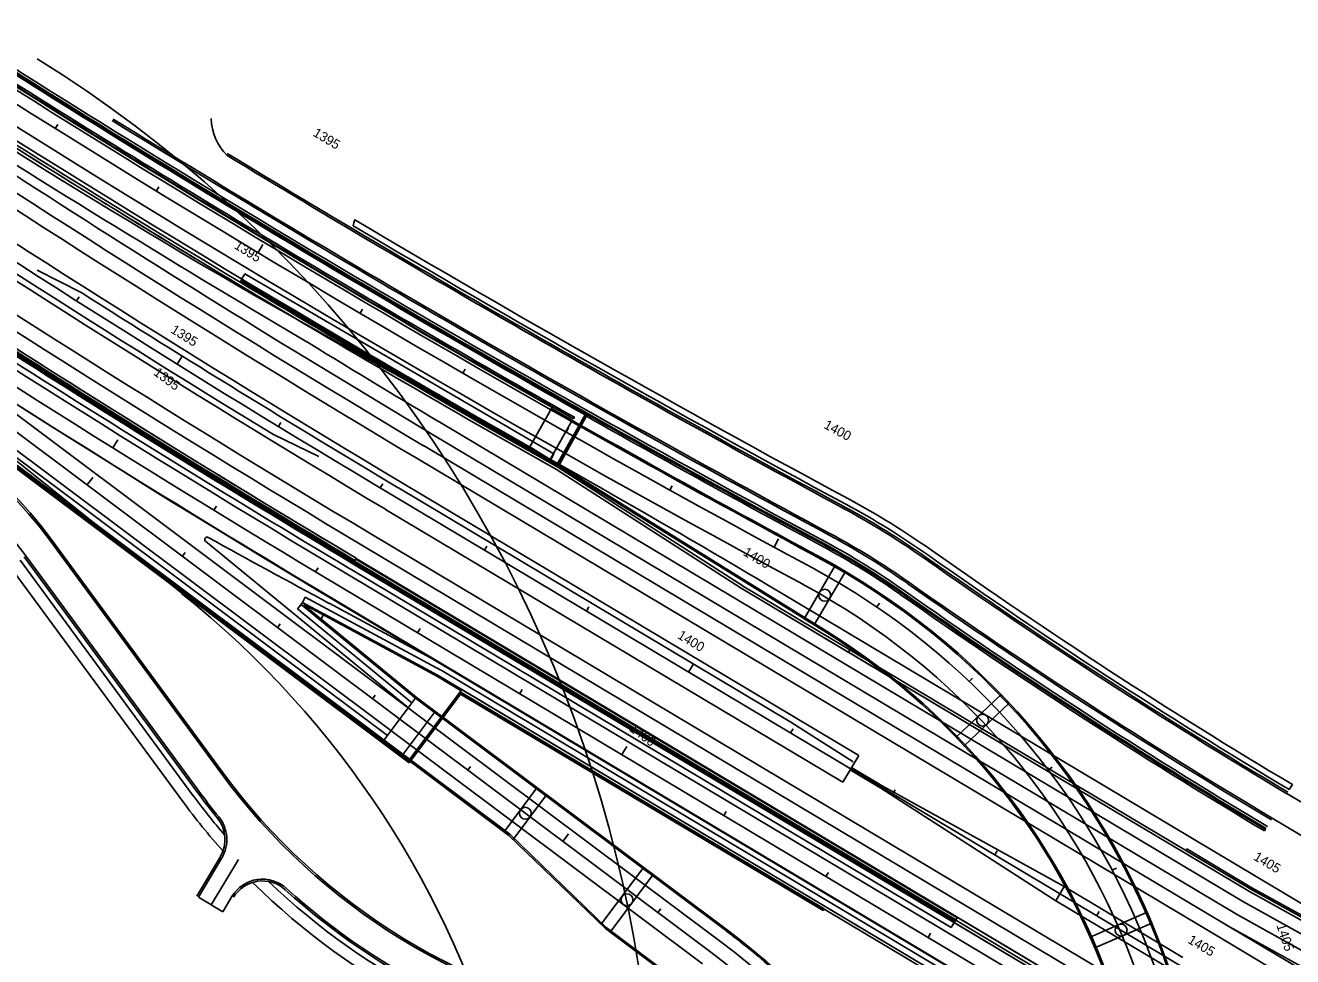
# Model space of a CAD drawing. Extents: x 2339272 to 2351734, y 366540 to 375057.
# Drawn here: x 2345972 to 2347038, y 369498 to 370281 of the extents above; entities that cross this region are included whole.
import ezdxf

# ---------------------------------------------------------------- set-up
doc = ezdxf.new("R2010")
doc.units = 0
for name, color, linetype in [('RD_HC_Cl', 7, 'Continuous'), ('RD_HC_CL_Rel', 7, 'Continuous'), ('RD_HC_Data_Tic', 7, 'Continuous'), ('RD_HC_Data_Tic_Rel', 7, 'Continuous'), ('RD_HC_TX_Rel_Sta50', 7, 'Continuous'), ('RD_HC_TX_Sta50', 7, 'Continuous'), ('RD_PD_Bridge', 7, 'Continuous'), ('RD_PD_Final_LnLine', 7, 'Continuous'), ('RD_PD_Final_TrvlWay', 7, 'Continuous'), ('RD_PD_FOC', 7, 'Continuous'), ('RD_PD_MedBWall', 7, 'Continuous'), ('RD_PD_MedGR', 7, 'Continuous'), ('RD_PD_NOISE-WALL-GM', 7, 'Continuous'), ('RD_PD_PaveShd', 7, 'Continuous'), ('RD_PD_SW', 7, 'Continuous'), ('RD_PD_WallFill', 7, 'Continuous')]:
    doc.layers.add(name, color=color, linetype=linetype)

msp = doc.modelspace()

# ---------------------------------------------------------------- linework, layer by layer
at = {"layer": 'RD_HC_Cl'}
for p, q in [((2345614.6, 370194.7), (2346103.4, 369803.5)), ((2345614.6, 370194.7), (2346103.4, 369803.5)), ((2345614.6, 370194.7), (2346103.4, 369803.5)), ((2345614.6, 370194.7), (2346103.4, 369803.5)), ((2345717.1, 370123.9), (2346548.7, 369501.6)), ((2346281.6, 369885.4), (2351112.4, 367003.2)), ((2346606.5, 369804.5), (2348463.1, 368696.8)), ((2346606.5, 369804.5), (2348463.1, 368696.8)), ((2346606.5, 369804.5), (2348463.1, 368696.8)), ((2346606.5, 369804.5), (2348463.1, 368696.8))]:
    msp.add_line(p, q, dxfattribs=at)
for centre, radius, start, end in [((2352034, 379865.6), 11400.7, 232.99132, 241.72492), ((2352152.8, 379726.2), 11459.2, 233.26372, 239.17851), ((2349158.4, 375253.9), 6000, 236.19528, 241.60251), ((2349158.4, 375253.9), 6000, 236.19528, 241.60251), ((2349158.4, 375253.9), 6000, 236.19528, 241.60251), ((2349158.4, 375253.9), 6000, 236.19528, 241.60251), ((2345401.1, 369318.9), 1100, 337.175, 58.1352), ((2345401.1, 369318.9), 1100, 337.175, 58.1352), ((2345401.1, 369318.9), 1100, 337.175, 58.1352), ((2345401.1, 369318.9), 1100, 337.175, 58.1352), ((2342405.1, 362762.6), 8200, 59.17851, 61.60251), ((2342405.1, 362762.6), 8200, 59.17851, 61.60251), ((2342405.1, 362762.6), 8200, 59.17851, 61.60251), ((2342405.1, 362762.6), 8200, 59.17851, 61.60251), ((2346341.6, 369282.7), 616, 339.5935, 61.7249), ((2345603.4, 369178.9), 800, 339.7746, 51.3248), ((2345603.4, 369178.9), 800, 339.7746, 51.3248), ((2345603.4, 369178.9), 800, 339.7746, 51.3248), ((2345603.4, 369178.9), 800, 339.7746, 51.3248), ((2346182, 369011.6), 612, 321.0938, 53.1918)]:
    msp.add_arc(centre, radius, start, end, dxfattribs=at)
at = {"layer": 'RD_HC_CL_Rel'}
for p, q in [((2346236.3, 369809.5), (2347935.6, 368795.6)), ((2346990.8, 369533.5), (2347672.4, 369155.9))]:
    msp.add_line(p, q, dxfattribs=at)
msp.add_arc((2352152.8, 379726.2), 11547.6, 233.26372, 239.17851, dxfattribs=at)
at = {"layer": 'RD_HC_Data_Tic'}
for p, q in [((2345997, 370194.5), (2345999.1, 370197.9)), ((2346082.1, 370141.9), (2346084.2, 370145.3)), ((2346167.6, 370090.1), (2346171.7, 370096.9)), ((2346015, 370049.4), (2346017.2, 370052.8)), ((2346253.6, 370039), (2346255.6, 370042.4)), ((2346099.7, 369996.2), (2346103.9, 370003)), ((2346340, 369988.7), (2346342, 369992.1)), ((2346184.8, 369943.8), (2346186.9, 369947.2)), ((2346426.8, 369939.1), (2346428.8, 369942.6)), ((2346023.7, 369894.4), (2346028.5, 369900.8)), ((2346270.4, 369892.1), (2346272.5, 369895.5)), ((2346514.1, 369890.3), (2346516.1, 369893.8)), ((2346601.8, 369842.3), (2346605.6, 369849.3)), ((2346103.8, 369834.5), (2346106.2, 369837.7)), ((2346358.1, 369839.8), (2346360.1, 369843.2)), ((2346688.2, 369792), (2346690.4, 369795.3)), ((2346443.9, 369788.6), (2346446, 369792)), ((2346183.9, 369774.5), (2346186.3, 369777.7)), ((2346529.8, 369737.3), (2346533.9, 369744.2)), ((2346765.9, 369729.3), (2346768.7, 369732.2)), ((2346263.9, 369714.6), (2346266.3, 369717.8)), ((2346615.7, 369686.1), (2346617.7, 369689.5)), ((2346344, 369654.7), (2346346.4, 369657.9)), ((2346832.5, 369654.8), (2346835.7, 369657.2)), ((2346701.6, 369634.8), (2346703.6, 369638.3)), ((2346424.1, 369594.8), (2346428.9, 369601.2)), ((2346787.5, 369583.6), (2346789.5, 369587)), ((2346886.2, 369570.6), (2346889.8, 369572.4)), ((2346504.1, 369534.9), (2346506.5, 369538.1)), ((2346873.3, 369532.4), (2346875.4, 369535.8))]:
    msp.add_line(p, q, dxfattribs=at)
at = {"layer": 'RD_HC_Data_Tic_Rel'}
for p, q in [((2346045.4, 369925.9), (2346049.6, 369932.7)), ((2346130.5, 369873.4), (2346132.6, 369876.8)), ((2346216.1, 369821.6), (2346218.1, 369825)), ((2346301.9, 369770.3), (2346304, 369773.8)), ((2346387.8, 369719.1), (2346389.8, 369722.5)), ((2346473.7, 369667.9), (2346477.8, 369674.7)), ((2346559.6, 369616.6), (2346561.6, 369620.1)), ((2346645.4, 369565.4), (2346647.5, 369568.8)), ((2346731.3, 369514.1), (2346733.4, 369517.6))]:
    msp.add_line(p, q, dxfattribs=at)
at = {"layer": 'RD_PD_Bridge'}
for p, q in [((2346414.5, 369958.9), (2346396.2, 369926.6)), ((2346431.3, 369948), (2346413.6, 369916.7)), ((2346645.9, 369770.4), (2346395.7, 369925.7)), ((2346646.5, 369771.4), (2346396.2, 369926.6)), ((2346665.5, 369755.9), (2346664.3, 369753.9)), ((2346858.3, 369638.2), (2346664.3, 369753.9)), ((2346859.4, 369640.2), (2346665.5, 369755.9)), ((2346272.9, 369679), (2346300.6, 369716.1)), ((2346300, 369715.2), (2346561.9, 369519.2)), ((2346300.6, 369716.1), (2346562.5, 369520.1)), ((2346288.9, 369667), (2346316.6, 369704.1)), ((2346272.9, 369679), (2346378.6, 369599.9)), ((2346273.6, 369679.9), (2346379.4, 369600.8)), ((2346374.6, 369602.9), (2346402.3, 369640)), ((2346382.2, 369596.5), (2346410.3, 369634)), ((2346859.4, 369640.2), (2346858.3, 369638.2)), ((2346379.4, 369600.8), (2346460.6, 369522.5)), ((2346378.6, 369599.9), (2346459.9, 369521.6)), ((2346456.3, 369525.1), (2346492, 369572.9)), ((2346463.9, 369518.6), (2346500, 369566.9)), ((2346845.9, 369556.8), (2346838.8, 369544.9)), ((2346845.9, 369556.8), (2346945.7, 369497.2)), ((2346838.8, 369544.9), (2346938.6, 369485.4)), ((2346459.9, 369521.6), (2346526.4, 369471.8)), ((2346460.6, 369522.5), (2346527.1, 369472.7)), ((2346922.6, 369515.9), (2346922.5, 369515.9))]:
    msp.add_line(p, q, dxfattribs=at)
for points in [[(2346653.2, 369827), (2346661.8, 369821.9), (2346635.6, 369776.9), (2346627, 369782)], [(2346792.7, 369718.4), (2346799.6, 369711.1), (2346761.7, 369675.1), (2346754.9, 369682.4)], [(2346915.7, 369535.2), (2346919.6, 369526), (2346871.7, 369505.2), (2346867.8, 369514.4)]]:
    msp.add_lwpolyline(points, close=True, dxfattribs=at)
for centre in [(2346644.4, 369801.9), (2346777.2, 369696.8), (2346777.2, 369696.8), (2346392.5, 369618.5), (2346478, 369545.7), (2346893.7, 369520.2)]:
    msp.add_circle(centre, 5, dxfattribs=at)
for centre, radius, start, end in [((2352034, 379865.6), 11390.7, 240.43629, 241.72492), ((2352034, 379865.6), 11389.6, 240.43628, 241.72492), ((2346341.6, 369282.7), 627.1, 339.5935, 61.7249), ((2346341.6, 369282.7), 626, 339.5935, 61.7249), ((2346341.6, 369282.7), 576, 339.5935, 58.038), ((2346341.6, 369282.7), 574.9, 339.5935, 58.038), ((2346182, 369011.6), 634, 51.3834, 53.1918), ((2346182, 369011.6), 635.1, 352.9805, 53.1918), ((2346182, 369011.6), 634, 31.6599, 51.3834)]:
    msp.add_arc(centre, radius, start, end, dxfattribs=at)
at = {"layer": 'RD_PD_Final_LnLine'}
for p, q in [((2345717.1, 370123.9), (2346548.7, 369501.6)), ((2346197.1, 370007.9), (2346312.9, 369938)), ((2346312.9, 369938), (2346990.8, 369533.5)), ((2346306.8, 369927.7), (2346984.8, 369523.1)), ((2346300.6, 369917.3), (2346978.7, 369512.8)), ((2346262.5, 369853.5), (2348279.8, 368650)), ((2345972.2, 369835.1), (2346117.2, 369637.9)), ((2346236.3, 369809.5), (2347935.6, 368795.6)), ((2346236.7, 369794.6), (2347945.2, 368775.3)), ((2346236.7, 369794.6), (2347945.2, 368775.3)), ((2346236.7, 369794.6), (2347945.2, 368775.3)), ((2346236.7, 369794.6), (2347945.2, 368775.3)), ((2347033.2, 369635), (2347131.4, 369576.4)), ((2347020.9, 369614.3), (2347119.1, 369555.8)), ((2346137.2, 369580.9), (2346117.4, 369548)), ((2346151.1, 369579.6), (2346128.2, 369541.5)), ((2346145.7, 369548.6), (2346137.9, 369535.6)), ((2347672.4, 369155.9), (2346990.8, 369533.5)), ((2346978.7, 369512.8), (2348317.9, 368713.8))]:
    msp.add_line(p, q, dxfattribs=at)
for centre, radius, start, end in [((2351872.8, 379241), 11000, 231.26372, 239.17851), ((2351872.8, 379241), 11000, 231.26372, 239.17851), ((2351872.8, 379241), 11000, 231.26372, 239.17851), ((2351872.8, 379241), 11000, 231.26372, 239.17851), ((2352152.8, 379726.2), 11410, 233.26372, 239.17851), ((2352152.8, 379726.2), 11422, 233.26372, 239.17851), ((2352152.8, 379726.2), 11496.3, 233.31776, 239.17851), ((2352152.8, 379726.2), 11547.6, 233.26372, 239.17851), ((2352152.8, 379726.2), 11398, 234.59863, 238.49864), ((2352034, 379865.6), 11368.2, 238.21382, 241.72492), ((2346172.4, 370203.3), 44.1, 180.7255, 225.5442), ((2352034, 379865.6), 11344.2, 238.70628, 241.72492), ((2345729.7, 369656.8), 325, 36.3291, 109.3829), ((2345729.7, 369656.8), 301, 36.3291, 109.3829), ((2346341.6, 369282.7), 672.5, 54.8366, 61.7249), ((2346341.6, 369282.7), 648.5, 54.8366, 61.7249), ((2346341.6, 369282.7), 616, 339.5935, 61.7249), ((2349486.4, 373746.7), 4788, 234.8366, 239.1785), ((2349486.4, 373746.7), 4812, 234.8366, 239.1785), ((2346569.9, 369970.9), 538, 216.3291, 260.6339), ((2346569.9, 369970.9), 562, 216.3291, 219.245), ((2346111.4, 369596.4), 30, 328.9635, 39.245), ((2346171.4, 369533.1), 30, 47.6839, 148.9808), ((2346569.9, 369970.9), 562, 227.6839, 260.6339), ((2346182, 369011.6), 612, 321.0938, 53.1918)]:
    msp.add_arc(centre, radius, start, end, dxfattribs=at)
at = {"layer": 'RD_PD_Final_TrvlWay'}
for p, q in [((2345710.1, 370114.1), (2346541.5, 369491.9)), ((2345882.8, 370014.8), (2346297.7, 369704.4)), ((2346319.1, 369948.3), (2346996.8, 369543.9)), ((2345991.5, 369849.3), (2346136.5, 369652.2)), ((2346123.6, 369847.2), (2346297.7, 369704.4)), ((2345972.2, 369835.1), (2346117.2, 369637.9)), ((2346256.4, 369843.2), (2348273.5, 368639.7)), ((2346242.4, 369819.8), (2347941.8, 368805.9)), ((2346217.6, 369806.6), (2347929.5, 368785.3)), ((2346227.6, 369795.1), (2346323.7, 369743.4)), ((2346297.7, 369704.4), (2346555.9, 369511.2)), ((2346117.4, 369548), (2346137.9, 369535.6)), ((2346996.8, 369543.9), (2347678.2, 369166.4)), ((2346984.8, 369523.1), (2348324.1, 368724.1)), ((2347390, 369298.6), (2346984.8, 369523.1))]:
    msp.add_line(p, q, dxfattribs=at)
for centre, radius, start, end in [((2352034, 379865.6), 11400.7, 232.99132, 241.72492), ((2352034, 379865.6), 11416.7, 232.99132, 241.72492), ((2352152.8, 379726.2), 11508.3, 233.26372, 239.17851), ((2352152.8, 379726.2), 11535.6, 233.26372, 239.17851), ((2352001.8, 379817.3), 11386.2, 235.48365, 239.38613), ((2352152.8, 379726.2), 11386, 238.49864, 239.17851), ((2352152.8, 379726.2), 11559.6, 237.15193, 239.17851), ((2346124.7, 369848.8), 2, 58.6047, 233.1918), ((2351708.8, 379983.8), 11569.6, 241.14705, 241.72088), ((2346341.6, 369282.7), 600, 339.5935, 61.7249), ((2346182, 369011.6), 624, 321.0938, 53.1918)]:
    msp.add_arc(centre, radius, start, end, dxfattribs=at)
at = {"layer": 'RD_PD_FOC'}
for p, q in [((2345992.7, 369850.2), (2346137.7, 369653)), ((2345971, 369834.2), (2346115.9, 369637)), ((2346135.9, 369581.7), (2346116.1, 369548.8))]:
    msp.add_line(p, q, dxfattribs=at)
for centre, radius, start, end in [((2352034, 379865.6), 11369.7, 238.21382, 241.72492), ((2352034, 379865.6), 11342.7, 238.70279, 241.72492), ((2345729.7, 369656.8), 326.5, 36.3291, 109.3829), ((2346341.6, 369282.7), 674, 54.8366, 61.7249), ((2346341.6, 369282.7), 647, 54.8366, 61.7249), ((2349486.4, 373746.7), 4786.5, 234.8366, 239.1785), ((2349486.4, 373746.7), 4813.5, 234.8366, 239.1785), ((2346569.9, 369970.9), 536.5, 216.3291, 260.6339), ((2346569.9, 369970.9), 563.5, 216.3291, 219.245), ((2346111.4, 369596.4), 28.5, 328.9635, 39.245), ((2346171.4, 369533.1), 28.5, 47.6839, 148.9808), ((2346569.9, 369970.9), 563.5, 227.6839, 260.6339)]:
    msp.add_arc(centre, radius, start, end, dxfattribs=at)
at = {"layer": 'RD_PD_MedBWall'}
for p, q in [((2345703.8, 370105.1), (2346289, 369667.1)), ((2345703.8, 370105.1), (2346273, 369679.1)), ((2345704.4, 370105.9), (2346273.6, 369679.9)), ((2346289.6, 369667.9), (2345704.4, 370105.9)), ((2346276.6, 369683.9), (2345707.2, 370110)), ((2346156.6, 370072.2), (2346154.1, 370067.9)), ((2346416.6, 369920.8), (2346156.6, 370072.2)), ((2346154.1, 370067.8), (2346153.6, 370067)), ((2346415.1, 369959.9), (2346413.9, 369957.9)), ((2346416.6, 369920.8), (2346414.1, 369916.5)), ((2346414.1, 369916.5), (2346413.5, 369915.4)), ((2346419.8, 369909.7), (2346575.4, 369809.7)), ((2346418.6, 369907.7), (2346574.1, 369807.7)), ((2346750.9, 369522.3), (2346245, 369824.1)), ((2346753.4, 369526.6), (2346247.5, 369828.4)), ((2346248.1, 369829.3), (2346753.9, 369527.4)), ((2346249.9, 369832.3), (2346248.9, 369830.6)), ((2346754.7, 369528.8), (2346248.9, 369830.6)), ((2346250.2, 369832.9), (2346249.2, 369831.2)), ((2346249.9, 369832.3), (2346755.8, 369530.5)), ((2346574.1, 369807.7), (2346664.2, 369754)), ((2346575.3, 369809.7), (2346665.4, 369756)), ((2346200.8, 369790.3), (2346204, 369794.2)), ((2346205.1, 369795.8), (2346204, 369794.2)), ((2346204, 369794.2), (2346300.1, 369715.3)), ((2346207.4, 369800.2), (2346205.1, 369795.8)), ((2346205.1, 369795.8), (2346319.1, 369734.5)), ((2346206.3, 369794), (2346206.1, 369793.7)), ((2346206.1, 369793.7), (2346300.7, 369716.1)), ((2346206.3, 369794), (2346318.6, 369733.6)), ((2346207.4, 369800.2), (2346321.5, 369738.9)), ((2346200.8, 369790.3), (2346297.1, 369711.3)), ((2346318.6, 369733.6), (2346338.6, 369721.6)), ((2346319.1, 369734.5), (2346339.2, 369722.5)), ((2346321.7, 369738.8), (2347066.1, 369294.6)), ((2346339.2, 369722.5), (2346337.8, 369720.6)), ((2346337.8, 369720.6), (2346872.1, 369401.8)), ((2346339.2, 369722.5), (2346873.3, 369403.8)), ((2346289, 369667.1), (2346289.6, 369667.9)), ((2346666.9, 369656.9), (2346665.7, 369654.9)), ((2346665.7, 369654.9), (2346691.6, 369639.5)), ((2346665.7, 369654.9), (2346691.5, 369639.5)), ((2346666.9, 369656.9), (2346692.8, 369641.5)), ((2346838.8, 369544.9), (2346691.5, 369639.5)), ((2346692.7, 369641.5), (2346845.9, 369556.8)), ((2346858.3, 369638.2), (2347001.8, 369552.6)), ((2346859.4, 369640.2), (2347002.9, 369554.6)), ((2347683, 369175.2), (2347001.8, 369552.6)), ((2347684.2, 369177.2), (2347002.9, 369554.6)), ((2346753.4, 369526.6), (2346750.9, 369522.3)), ((2346753.9, 369527.4), (2346753.4, 369526.6)), ((2346753.9, 369527.4), (2346753.4, 369526.6)), ((2346753.4, 369526.6), (2347946.9, 368814.5)), ((2346754.6, 369528.6), (2347948.1, 368816.5)), ((2346755.8, 369530.5), (2346754.7, 369528.8))]:
    msp.add_line(p, q, dxfattribs=at)
for centre, radius, start, end in [((2352002, 379817.2), 11374.2, 235.499, 239.0438), ((2352002, 379817.2), 11371.8, 235.499, 239.0438), ((2352034, 379865.6), 11378.2, 237.52318, 241.72492), ((2352034, 379865.6), 11376.2, 237.52318, 241.72492), ((2352034, 379865.6), 11390.7, 237.52318, 240.43629), ((2352034, 379865.6), 11388.4, 237.52318, 240.43629), ((2352152.8, 379726.2), 11520.3, 235.61364, 239.17851), ((2352152.8, 379726.2), 11530.6, 235.61364, 239.17851), ((2352152.8, 379726.2), 11525.6, 235.61364, 239.17851), ((2352152.8, 379726.2), 11524.6, 235.61364, 239.17851), ((2352152.8, 379726.2), 11522.3, 235.61364, 239.17851), ((2352002, 379817.2), 11374.2, 239.0438, 239.38929), ((2352034, 379865.6), 11432.1, 239.03094, 240.58117), ((2352002, 379817.2), 11371.8, 239.0438, 239.38929), ((2352034, 379865.6), 11429.8, 239.03094, 240.58117), ((2352034, 379865.6), 11427.7, 239.03094, 240.43661), ((2352034, 379865.6), 11426.7, 239.03094, 240.43661), ((2352034, 379865.6), 11390.7, 240.42989, 240.43629), ((2346341.6, 369282.7), 640.5, 54.8366, 61.7249), ((2346341.6, 369282.7), 638.5, 54.8366, 61.7249), ((2349486.4, 373746.7), 4822, 234.8366, 239.1785), ((2349486.4, 373746.7), 4820, 234.8366, 239.1785)]:
    msp.add_arc(centre, radius, start, end, dxfattribs=at)
at = {"layer": 'RD_PD_MedGR'}
for p, q in [((2346019.3, 370056.2), (2345981.7, 370075.4)), ((2346180.7, 369937), (2346218.7, 369918.6)), ((2346285.7, 369892.3), (2346616, 369695.2)), ((2346668.3, 369661.7), (2346616, 369695.2))]:
    msp.add_line(p, q, dxfattribs=at)
for radius, start, end in [(11467.2, 233.26372, 238.61364), (11451.2, 237.61364, 239.17851)]:
    msp.add_arc((2352152.8, 379726.2), radius, start, end, dxfattribs=at)
at = {"layer": 'RD_PD_NOISE-WALL-GM'}
for p, q in [((2346433.8, 369951.7), (2346433, 369950.3)), ((2347014.5, 369603.6), (2347015.2, 369604.9)), ((2346948.2, 369587.3), (2346949, 369588.6)), ((2346948.2, 369587.3), (2347002.9, 369554.6)), ((2346949, 369588.6), (2347003.7, 369555.9)), ((2347684.2, 369177.2), (2347002.9, 369554.6)), ((2347684.9, 369178.5), (2347003.7, 369555.9))]:
    msp.add_line(p, q, dxfattribs=at)
for centre, radius, start, end in [((2352034, 379865.6), 11387.9, 237.52318, 240.53856), ((2352034, 379865.6), 11386.4, 237.52318, 240.53856), ((2352034, 379865.6), 11380.7, 240.58136, 241.72492), ((2352034, 379865.6), 11379.2, 240.58136, 241.72492), ((2346341.6, 369282.7), 636, 54.8366, 61.7249), ((2346341.6, 369282.7), 637.5, 54.8366, 61.7249), ((2349486.4, 373746.7), 4823, 234.8366, 239.1785), ((2349486.4, 373746.7), 4824.5, 234.8366, 239.1785)]:
    msp.add_arc(centre, radius, start, end, dxfattribs=at)
at = {"layer": 'RD_PD_PaveShd'}
for p, q in [((2345704.4, 370105.9), (2346273.6, 369679.9)), ((2346288.3, 369896.7), (2346673, 369667.2)), ((2346274.8, 369874.1), (2346659.6, 369644.6)), ((2346247.5, 369828.4), (2347946.9, 368814.5)), ((2346250.2, 369832.9), (2347949.6, 368819)), ((2346250.2, 369832.9), (2348267.5, 368629.3)), ((2346574.1, 369807.7), (2346858.3, 369638.2)), ((2346223, 369786.2), (2346220.1, 369780.9)), ((2346223, 369786.2), (2346319.1, 369734.5)), ((2346220.1, 369780.9), (2346300.1, 369715.3)), ((2346319.1, 369734.5), (2347063.5, 369290.3)), ((2346659.6, 369644.6), (2346673, 369667.2)), ((2346858.3, 369638.2), (2347001.8, 369552.6)), ((2347683, 369175.2), (2347001.8, 369552.6))]:
    msp.add_line(p, q, dxfattribs=at)
for centre, radius, start, end in [((2352034, 379865.6), 11426.7, 233.08852, 240.43661), ((2352152.8, 379726.2), 11446, 233.26372, 239.17851), ((2352152.8, 379726.2), 11472.3, 233.26372, 239.17851), ((2352152.8, 379726.2), 11520.3, 233.61364, 239.17851), ((2352002, 379817.2), 11374.2, 235.48286, 239.0438), ((2352034, 379865.6), 11432.1, 239.03094, 240.58117)]:
    msp.add_arc(centre, radius, start, end, dxfattribs=at)
at = {"layer": 'RD_PD_SW'}
for p, q in [((2346247.7, 370112.7), (2346248.1, 370115.2)), ((2346248.1, 370115.2), (2346249, 370117.8)), ((2345959.3, 369825.6), (2346104.3, 369628.5)), ((2345967.4, 369831.5), (2346112.3, 369634.4)), ((2347037.8, 369642.7), (2347035.2, 369638.4))]:
    msp.add_line(p, q, dxfattribs=at)
for centre, radius, start, end in [((2352034, 379865.6), 11340.2, 239.31989, 241.72492), ((2352034, 379865.6), 11335.2, 239.31256, 241.72492), ((2346341.6, 369282.7), 676.5, 54.8366, 61.7249), ((2346341.6, 369282.7), 681.5, 54.8366, 61.7249), ((2349486.4, 373746.7), 4784, 234.8366, 239.1785), ((2349486.4, 373746.7), 4779, 234.8366, 239.1785), ((2346569.9, 369970.9), 568, 216.3291, 220.7637), ((2346569.9, 369970.9), 578, 216.3291, 221.6767), ((2346569.9, 369970.9), 578, 225.2522, 260.6339), ((2346569.9, 369970.9), 568, 226.1651, 260.6339)]:
    msp.add_arc(centre, radius, start, end, dxfattribs=at)
at = {"layer": 'RD_PD_WallFill'}
for p, q in [((2345702.9, 370103.9), (2346294.9, 369660.9)), ((2346294.9, 369660.9), (2345702.9, 370103.9)), ((2346294.8, 369661.6), (2345703.2, 370104.3)), ((2346294.7, 369662.3), (2345703.5, 370104.7)), ((2345703.8, 370105.1), (2346294.6, 369663)), ((2345703.8, 370105.1), (2346294.6, 369663)), ((2345703.8, 370105.1), (2346294.6, 369663)), ((2346153.4, 370066.7), (2346152.7, 370065.5)), ((2346419.4, 369912), (2346442.9, 369953.6)), ((2346419.6, 369911.3), (2346443.6, 369953.8)), ((2346419.8, 369910.6), (2346444.2, 369954)), ((2346420, 369909.9), (2346444.9, 369954.2)), ((2346248.1, 369829.3), (2346753.9, 369527.4)), ((2346248.3, 369829.7), (2346754.2, 369527.9)), ((2346248.6, 369830.1), (2346754.4, 369528.3)), ((2346248.8, 369830.5), (2346754.7, 369528.7)), ((2346294.6, 369663), (2346337.8, 369720.6)), ((2346294.7, 369662.3), (2346337.9, 369720)), ((2346294.8, 369661.6), (2346338, 369719.3)), ((2346294.9, 369660.9), (2346338.1, 369718.6)), ((2346337.8, 369720.6), (2346643.8, 369538)), ((2346337.9, 369720), (2346643.6, 369537.6)), ((2346338, 369719.3), (2346643.3, 369537.2)), ((2346338.1, 369718.6), (2346643, 369536.7)), ((2346294.6, 369663), (2346294.9, 369660.9)), ((2346294.6, 369663), (2346294.9, 369660.9)), ((2346643, 369536.7), (2346643.8, 369538)), ((2346754.7, 369528.7), (2346753.9, 369527.4))]:
    msp.add_line(p, q, dxfattribs=at)
for centre, radius, start, end in [((2352034, 379865.6), 11380.2, 237.52318, 240.5738), ((2352034, 379865.6), 11379.7, 237.52318, 240.57632), ((2352034, 379865.6), 11379.2, 237.52318, 240.57884), ((2352034, 379865.6), 11378.7, 237.52318, 240.58136), ((2352152.8, 379726.2), 11524.6, 235.61364, 239.17851), ((2352152.8, 379726.2), 11524.1, 235.61364, 239.17851), ((2352152.8, 379726.2), 11523.6, 235.61364, 239.17851), ((2352152.8, 379726.2), 11523.1, 235.61364, 239.17851), ((2352034, 379865.6), 11429.5, 239.03094, 240.58117), ((2352034, 379865.6), 11429, 239.03094, 240.57867), ((2352034, 379865.6), 11428.5, 239.03094, 240.57616), ((2352034, 379865.6), 11428, 239.03094, 240.57366)]:
    msp.add_arc(centre, radius, start, end, dxfattribs=at)

# ---------------------------------------------------------------- texts
at = {"layer": 'RD_HC_TX_Rel_Sta50'}
for s, rotation, p in [('1395', 328.0693, (2346093.5, 370023.2)), ('1400', 329.1785, (2346519.8, 369766.1)), ('1405', 329.1785, (2346949.2, 369509.9))]:
    msp.add_text(s, height=8, rotation=rotation, dxfattribs=at).set_placement(p)
at = {"layer": 'RD_HC_TX_Sta50'}
for s, rotation, p in [('1395', 329.0317, (2346213.2, 370188.7)), ('1395', 328.1136, (2346146.9, 370094.1)), ('1395', 323.1918, (2346079.1, 369987.8)), ('1400', 331.5445, (2346643, 369942.8)), ('1400', 329.1785, (2346575.1, 369836)), ('1400', 323.1918, (2346479.4, 369688.3)), ('1405', 329.1785, (2347004.5, 369579.8)), ('1405', 288.558, (2347024.3, 369524.2))]:
    msp.add_text(s, height=8, rotation=rotation, dxfattribs=at).set_placement(p)

doc.saveas('drawing.dxf')
